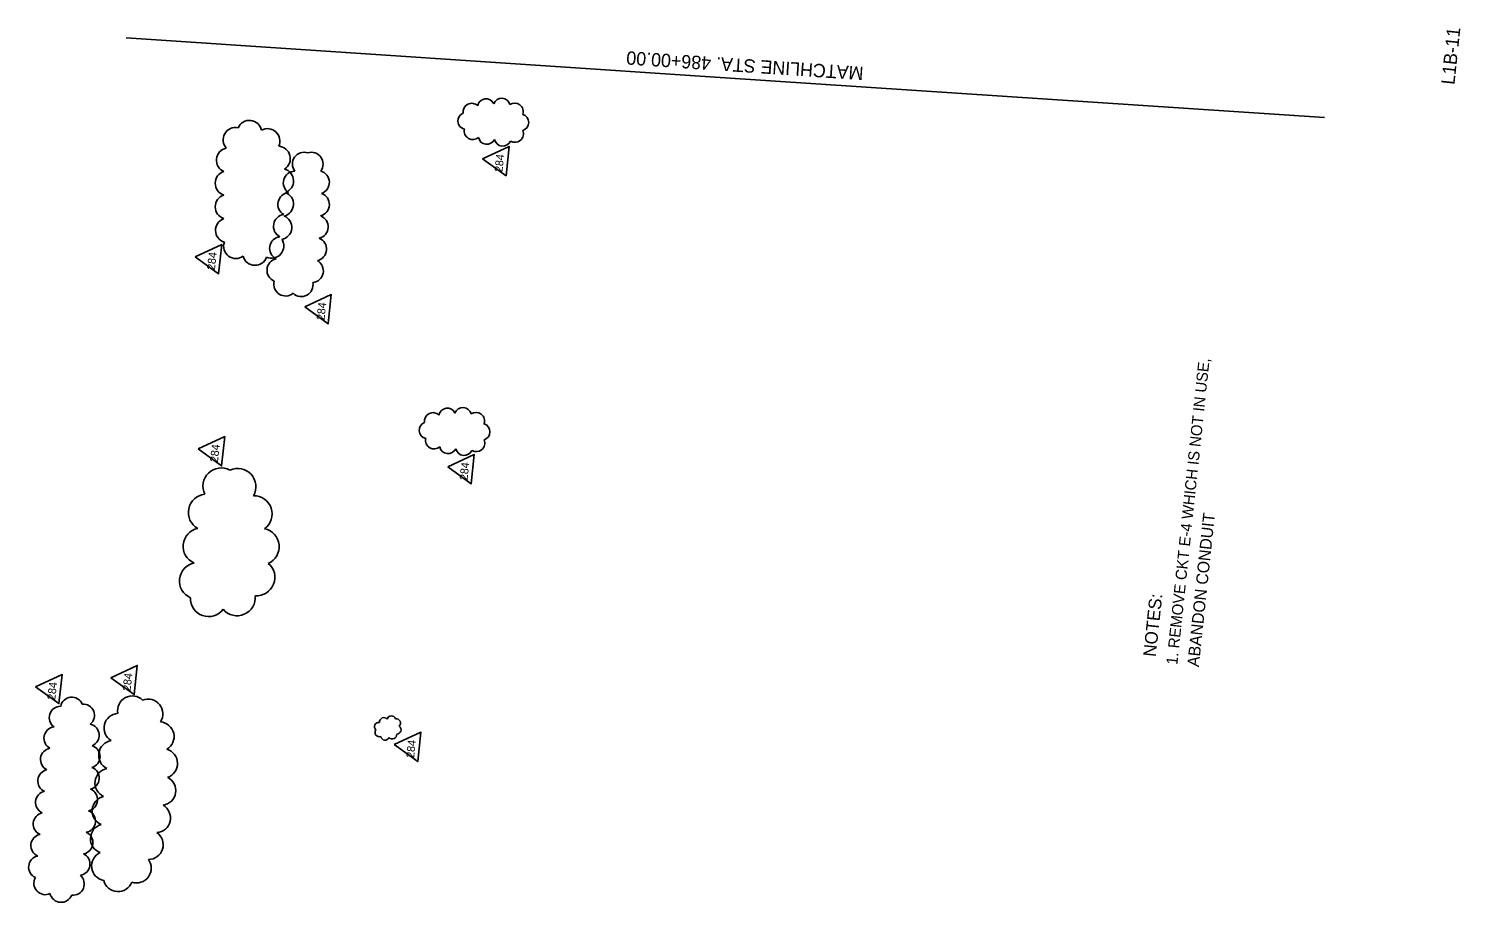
# Model space of a CAD drawing. Extents: x 930797 to 931706, y 623569 to 624777.
# Drawn here: x 930848 to 931706, y 624253 to 624777 of the extents above; entities that cross this region are included whole.
import ezdxf

# ---------------------------------------------------------------- set-up
doc = ezdxf.new("R2010")
doc.units = 0
for name, color, linetype in [('Cloud_dp', 7, 'Continuous'), ('MatchLines_dp', 7, 'Continuous'), ('TextShtNo', 7, 'Continuous')]:
    doc.layers.add(name, color=color, linetype=linetype)

msp = doc.modelspace()

# ---------------------------------------------------------------- linework, layer by layer
at = {"layer": 'Cloud_dp'}
for points in [[(931119.9, 624698.79), (931133.95, 624688.63), (931135.81, 624706.19)], [(930947.55, 624640.09), (930961.6, 624629.93), (930963.46, 624647.49)], [(931013.22, 624609.99), (931027.28, 624599.84), (931029.14, 624617.39)], [(930949.35, 624524.87), (930963.41, 624514.71), (930965.27, 624532.26)], [(931098.98, 624514.12), (931113.03, 624503.96), (931114.89, 624521.51)], [(930851.82, 624382.36), (930865.88, 624372.2), (930867.74, 624389.76)], [(930896.95, 624387.75), (930911.01, 624377.6), (930912.87, 624395.15)], [(931066.96, 624347.65), (931081.01, 624337.5), (931082.87, 624355.05)]]:
    msp.add_lwpolyline(points, close=True, dxfattribs=at)
for centre, radius, start, end in [((931121.96, 624729.66), 5.08, 25.33057, 170.33057), ((931131.3, 624730.03), 5.09, 14.26202, 159.26202), ((931110.18, 624721.48), 5.08, 112.02139, 257.02139), ((931113.29, 624726.98), 5.08, 43.99781, 188.99781), ((931139.16, 624727.13), 5.08, 340.16605, 125.16605), ((931142.46, 624720.55), 5.08, 288.08263, 73.08263), ((930971.69, 624710.15), 7.39, 77.41148, 222.41148), ((930980.08, 624714.44), 7.39, 11.63338, 156.63338), ((930990.96, 624709.5), 7.39, 334.51997, 119.51997), ((931113.99, 624715.4), 5.08, 167.16603, 312.16603), ((931139.35, 624713.74), 5.08, 237.9796, 22.9796), ((931122.4, 624712.56), 5.08, 190.52587, 335.52587), ((931132, 624711.46), 5.08, 191.45697, 336.45697), ((930967.73, 624697.93), 7.39, 101.68485, 246.68485), ((930997.22, 624698.94), 7.39, 301.81941, 86.81941), ((931012.9, 624695.67), 7.05, 72.36243, 217.36243), ((931017.22, 624695.69), 7.04, 323.06323, 108.06323), ((930966.99, 624684.09), 7.39, 107.2087, 252.2087), ((931007.45, 624684.34), 7.05, 91.20244, 236.20244), ((930999.17, 624685.53), 7.39, 289.74062, 74.74062), ((931020.98, 624684.66), 7.05, 289.63133, 74.63133), ((930966.99, 624670.02), 7.39, 107.77433, 252.77433), ((931004.2, 624671.47), 7.05, 95.51814, 240.51814), ((930999.1, 624671.65), 7.39, 284.7384, 69.7384), ((931020.96, 624671.39), 7.05, 285.16952, 70.16952), ((931001.58, 624658.34), 7.05, 96.93202, 241.93202), ((930998.09, 624657.7), 7.39, 281.97171, 66.97171), ((931020.28, 624658.01), 7.05, 284.00057, 69.00057), ((930967.15, 624655.95), 7.39, 108.55277, 253.55277), ((930972.03, 624646.4), 7.39, 160.47727, 305.47727), ((930993.33, 624646.61), 7.39, 246.55924, 31.55924), ((930999.28, 624645.14), 7.05, 98.22414, 243.22414), ((931019.29, 624644.66), 7.05, 282.56823, 67.56823), ((930983.44, 624642.33), 7.39, 195.25679, 340.25679), ((930997.66, 624631.98), 7.05, 102.80347, 247.80347), ((931017.39, 624631.63), 7.05, 275.81117, 60.81117), ((931001.8, 624623.59), 7.05, 164.72935, 309.72935), ((931011.19, 624623.26), 7.05, 226.12902, 11.12902), ((931090.08, 624541.56), 5.08, 43.99781, 188.99781), ((931098.74, 624544.24), 5.08, 25.33057, 170.33057), ((931108.09, 624544.61), 5.09, 14.26202, 159.26202), ((931115.94, 624541.72), 5.08, 340.16605, 125.16605), ((931086.96, 624536.06), 5.08, 112.02139, 257.02139), ((931119.24, 624535.14), 5.08, 288.08263, 73.08263), ((931090.78, 624529.98), 5.08, 167.16603, 312.16603), ((931116.14, 624528.32), 5.08, 237.9796, 22.9796), ((931099.18, 624527.14), 5.08, 190.52587, 335.52587), ((931108.79, 624526.05), 5.08, 191.45697, 336.45697), ((930963.15, 624502.56), 10.95, 61.37004, 206.37004), ((930973.07, 624502.28), 10.94, 330.27128, 115.27128), ((930954.43, 624486.8), 10.95, 95.73535, 240.73535), ((930982.75, 624485.91), 10.95, 305.9231, 90.9231), ((930951.25, 624466.52), 10.95, 101.43225, 246.43225), ((930987, 624466.31), 10.95, 293.58564, 78.58564), ((930949.05, 624445.76), 10.95, 101.45697, 246.45697), ((930984.43, 624447.83), 10.95, 265.54808, 50.54808), ((930955.62, 624435.34), 10.95, 178.00633, 323.00633), ((930972.68, 624435.86), 10.95, 220.49501, 5.49501), ((930873.64, 624369.25), 6.81, 23.57216, 168.57216), ((930880.39, 624365.18), 6.82, 309.27142, 94.27142), ((930909.89, 624368.02), 8.84, 45.50384, 190.50384), ((930919.36, 624366.11), 8.84, 326.70602, 111.70602), ((930866.91, 624363.78), 6.82, 89.51449, 234.51449), ((930901.8, 624357.59), 8.84, 93.86796, 238.86796), ((931060.68, 624361.21), 2.61, 39.76879, 184.76879), ((931065.22, 624362.23), 2.61, 20.59875, 165.59875), ((930863.74, 624351.46), 6.82, 96.70449, 241.70449), ((930883.24, 624353.24), 6.82, 292.60351, 77.60351), ((930926.09, 624352.44), 8.84, 300.70183, 85.70183), ((931057.72, 624358.41), 2.61, 82.00268, 227.00268), ((931058.05, 624354.96), 2.61, 143.94065, 288.94065), ((931068.06, 624360.57), 2.61, 313.66516, 98.66516), ((931068.37, 624356.54), 2.61, 270.11717, 55.11717), ((930883.73, 624340.47), 6.82, 286.75597, 71.75597), ((930898.59, 624341.29), 8.84, 98.89208, 243.89208), ((931061.46, 624352.96), 2.61, 190.33918, 335.33918), ((931065.78, 624353.62), 2.61, 221.92349, 6.92349), ((930861.65, 624338.74), 6.82, 99.60537, 244.60537), ((930928.18, 624336.34), 8.84, 289.14173, 74.14173), ((930860.05, 624325.89), 6.82, 101.19386, 246.19386), ((930883.25, 624327.58), 6.82, 283.97002, 68.97002), ((930896.34, 624324.66), 8.84, 100.69802, 245.69802), ((930882.26, 624314.68), 6.82, 282.26191, 67.26191), ((930927.1, 624320.09), 8.84, 278.2415, 63.2415), ((930858.65, 624312.98), 6.82, 101.45697, 246.45697), ((930894.65, 624307.98), 8.84, 102.72948, 247.72948), ((930857.28, 624300.04), 6.82, 101.45697, 246.45697), ((930880.96, 624301.78), 6.82, 281.25094, 66.25094), ((930923.92, 624303.7), 8.84, 274.78205, 59.78205), ((930879.46, 624288.89), 6.82, 280.46086, 65.46086), ((930893.6, 624291.26), 8.84, 105.0775, 250.0775), ((930919.56, 624287.67), 8.84, 269.79559, 54.79559), ((930855.91, 624287.11), 6.82, 101.45697, 246.45697), ((930854.55, 624274.18), 6.82, 101.45697, 246.45697), ((930877.69, 624276.07), 6.82, 278.84036, 63.84036), ((930894.31, 624274.92), 8.84, 114.83601, 259.83601), ((930912.4, 624273.59), 8.84, 251.28776, 36.28776), ((930874.27, 624264.18), 6.82, 264.06545, 49.06545), ((930857.72, 624264.52), 6.82, 149.94186, 294.94186), ((930901.31, 624268.37), 8.83, 194.10354, 339.10354), ((930867.23, 624259.92), 6.82, 193.38287, 338.38287)]:
    msp.add_arc(centre, radius, start, end, dxfattribs=at)
at = {"layer": 'MatchLines_dp'}
msp.add_lwpolyline([(931624.53, 624723.55), (931265.32, 624747.4), (930906.11, 624771.25)], dxfattribs=at)

# ---------------------------------------------------------------- texts
at = {"layer": 'Cloud_dp'}
for s, height, p in [('284', 4.799, (931131.74, 624690.67)), ('284', 4.799, (930959.39, 624631.97)), ('284', 4.799, (931025.07, 624601.87)), ('1. REMOVE CKT E-4 WHICH IS NOT IN USE,', 6.6692, (931536.36, 624395.26)), ('284', 4.799, (930961.2, 624516.74)), ('284', 4.799, (931110.82, 624506)), ('ABANDON CONDUIT', 7.0877, (931549.27, 624393.99)), ('NOTES:', 7.624, (931523.45, 624400.03)), ('284', 4.799, (930908.8, 624379.63)), ('284', 4.799, (930863.67, 624374.24)), ('284', 4.799, (931078.8, 624339.53))]:
    msp.add_text(s, height=height, rotation=83.95697, dxfattribs=at).set_placement(p)
at = {"layer": 'MatchLines_dp'}
msp.add_text('MATCHLINE STA. 486+00.00', height=8, rotation=176.20126, dxfattribs=at).set_placement((931348.45, 624753.91))
at = {"layer": 'TextShtNo'}
msp.add_text('L1B-11', height=8, rotation=83.95697, dxfattribs=at).set_placement((931702.49, 624742.94))

doc.saveas('drawing.dxf')
